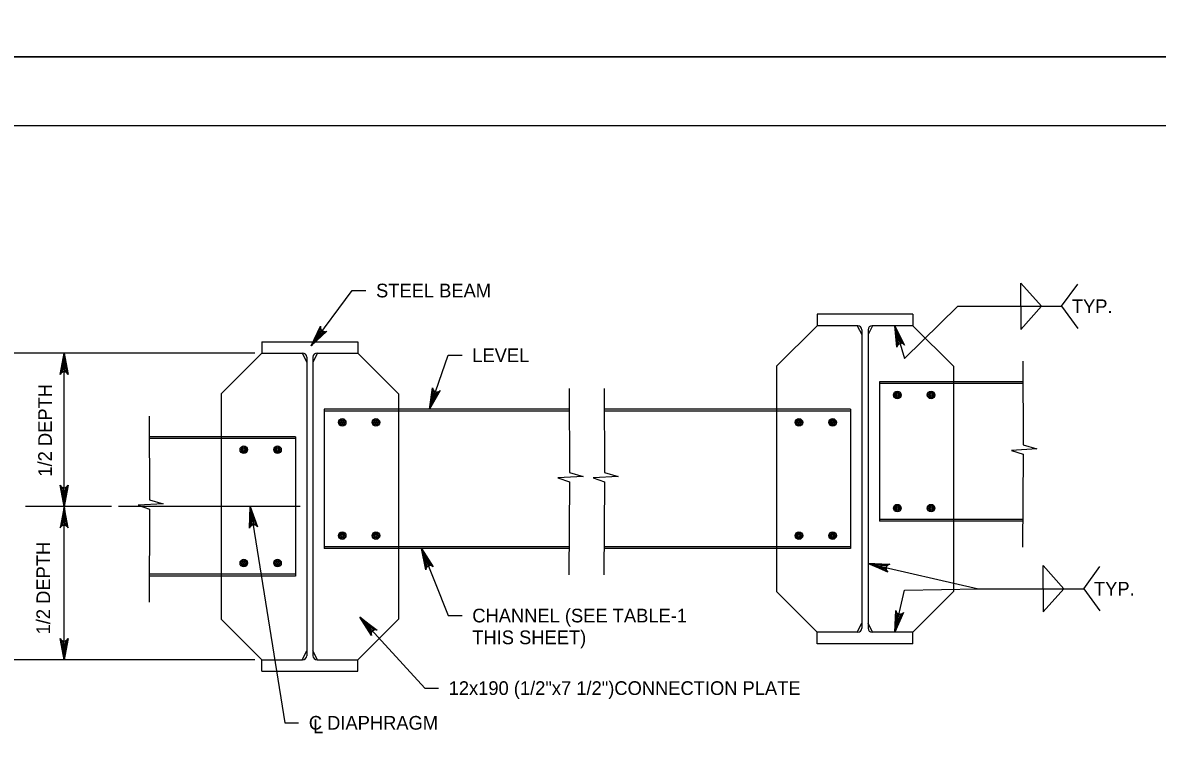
# Model space of a CAD drawing. Extents: x 638175 to 640495, y 294277 to 298435.
# Drawn here: x 639649.2 to 639897.7, y 297690.7 to 297849 of the extents above; entities that cross this region are included whole.
import ezdxf

# ---------------------------------------------------------------- set-up
doc = ezdxf.new("R2010")
doc.units = 0
for name, color, linetype in [('2', 7, 'Continuous'), ('3', 7, 'Continuous'), ('4', 7, 'Continuous'), ('5', 7, 'Continuous'), ('PLT-BNDY', 7, 'Continuous')]:
    doc.layers.add(name, color=color, linetype=linetype)

msp = doc.modelspace()

# ---------------------------------------------------------------- linework, layer by layer
at = {"layer": '2'}
msp.add_line((639316.46, 297826.46), (640102.46, 297826.46), dxfattribs=at)
for points in [[(639658.23, 297776.59), (639659.1, 297771.93), (639658.85, 297772.29), (639658.54, 297772.47), (639658.23, 297772.53), (639657.91, 297772.47), (639657.6, 297772.29), (639657.35, 297771.93), (639658.23, 297776.59), (639657.6, 297772.29), (639657.91, 297772.47), (639658.23, 297776.59), (639658.23, 297772.53), (639658.54, 297772.47), (639658.23, 297776.59), (639658.85, 297772.29)], [(639658.23, 297743.02), (639657.35, 297747.68), (639657.6, 297747.32), (639657.91, 297747.13), (639658.23, 297747.08), (639658.54, 297747.13), (639658.85, 297747.32), (639659.1, 297747.68), (639658.23, 297743.02), (639658.85, 297747.32), (639658.54, 297747.13), (639658.23, 297743.02), (639658.23, 297747.08), (639657.91, 297747.13), (639658.23, 297743.02), (639657.6, 297747.32)], [(639658.23, 297743.02), (639657.35, 297738.36), (639657.6, 297738.71), (639657.91, 297738.9), (639658.23, 297738.95), (639658.54, 297738.9), (639658.85, 297738.71), (639659.1, 297738.36), (639658.23, 297743.02), (639658.85, 297738.71), (639658.54, 297738.9), (639658.23, 297743.02), (639658.23, 297738.95), (639657.91, 297738.9), (639658.23, 297743.02), (639657.6, 297738.71)], [(639658.23, 297709.44), (639657.35, 297714.1), (639657.6, 297713.75), (639657.91, 297713.56), (639658.23, 297713.51), (639658.54, 297713.56), (639658.85, 297713.75), (639659.1, 297714.1), (639658.23, 297709.44), (639658.85, 297713.75), (639658.54, 297713.56), (639658.23, 297709.44), (639658.23, 297713.51), (639657.91, 297713.56), (639658.23, 297709.44), (639657.6, 297713.75)]]:
    msp.add_lwpolyline(points, dxfattribs=at)
at = {"layer": '3'}
for p, q in [((639867.84, 297791.93), (639872.38, 297786.85)), ((639867.84, 297786.85), (639867.84, 297791.93)), ((639876.75, 297786.85), (639880.32, 297791.69)), ((639712.33, 297778.21), (639721.32, 297790.3)), ((639721.32, 297790.3), (639724.32, 297790.3)), ((639842.3, 297775.45), (639854.05, 297786.85)), ((639854.05, 297786.85), (639876.75, 297786.85)), ((639867.84, 297781.76), (639872.38, 297786.85)), ((639867.84, 297786.85), (639867.84, 297781.76)), ((639876.75, 297786.85), (639880.32, 297782.01)), ((639840.22, 297782.6), (639842.3, 297775.45)), ((639700.02, 297776.59), (639634.16, 297776.59)), ((639658.23, 297743.02), (639658.23, 297776.59)), ((639738.25, 297764.29), (639742.4, 297776.14)), ((639742.4, 297776.14), (639745.4, 297776.14)), ((639868.25, 297774.83), (639868.31, 297756.48)), ((639768.85, 297768.82), (639768.91, 297750.46)), ((639776.57, 297768.82), (639776.63, 297750.46)), ((639676.89, 297762.81), (639676.95, 297744.45)), ((639868.31, 297756.48), (639871.31, 297755.6)), ((639871.31, 297755.6), (639865.79, 297755.29)), ((639865.79, 297755.29), (639868.3, 297754.43)), ((639868.3, 297754.43), (639868.18, 297734.08)), ((639771.92, 297749.58), (639766.4, 297749.28)), ((639766.4, 297749.28), (639768.91, 297748.42)), ((639768.91, 297750.46), (639771.92, 297749.58)), ((639779.63, 297749.58), (639774.11, 297749.28)), ((639774.11, 297749.28), (639776.63, 297748.42)), ((639776.63, 297750.46), (639779.63, 297749.58)), ((639768.91, 297748.42), (639768.79, 297728.06)), ((639776.63, 297748.42), (639776.5, 297728.06)), ((639676.95, 297744.45), (639679.96, 297743.57)), ((639668.59, 297743.02), (639649.76, 297743.02)), ((639658.23, 297709.44), (639658.23, 297743.02)), ((639679.96, 297743.57), (639674.44, 297743.26)), ((639674.44, 297743.26), (639676.95, 297742.41)), ((639676.95, 297742.41), (639676.83, 297722.05)), ((639698.98, 297743.02), (639706.59, 297695.63)), ((639736.53, 297733.77), (639742.4, 297719.13)), ((639834.37, 297730.53), (639858.54, 297725)), ((639872.68, 297730.08), (639877.21, 297725)), ((639872.68, 297725), (639872.68, 297730.08)), ((639881.59, 297725), (639885.16, 297729.84)), ((639840.22, 297715.46), (639842.3, 297724.66)), ((639842.3, 297724.66), (639858.54, 297725)), ((639858.54, 297725), (639881.59, 297725)), ((639872.68, 297725), (639872.68, 297719.92)), ((639872.68, 297719.92), (639877.21, 297725)), ((639881.59, 297725), (639885.16, 297720.16)), ((639742.4, 297719.13), (639745.4, 297719.13)), ((639723.05, 297718.78), (639737.22, 297703.23)), ((639700.02, 297709.44), (639634.16, 297709.44)), ((639737.22, 297703.23), (639740.22, 297703.23)), ((639706.59, 297695.63), (639709.59, 297695.63))]:
    msp.add_line(p, q, dxfattribs=at)
for points in [[(639712.33, 297778.21), (639714.41, 297782.47), (639714.39, 297782.04), (639714.53, 297781.7), (639714.75, 297781.47), (639715.03, 297781.33), (639715.4, 297781.29), (639715.81, 297781.43), (639712.33, 297778.21), (639715.4, 297781.29), (639715.03, 297781.33), (639712.33, 297778.21), (639714.75, 297781.47), (639714.53, 297781.7), (639712.33, 297778.21), (639714.39, 297782.04)], [(639840.22, 297782.6), (639842.36, 297778.37), (639842.02, 297778.65), (639841.67, 297778.74), (639841.35, 297778.7), (639841.07, 297778.56), (639840.82, 297778.3), (639840.68, 297777.89), (639840.22, 297782.6), (639840.82, 297778.3), (639841.07, 297778.56), (639840.22, 297782.6), (639841.35, 297778.7), (639841.67, 297778.74), (639840.22, 297782.6), (639842.02, 297778.65)], [(639738.25, 297764.29), (639738.97, 297768.97), (639739.08, 297768.55), (639739.32, 297768.27), (639739.6, 297768.12), (639739.91, 297768.07), (639740.26, 297768.14), (639740.62, 297768.4), (639738.25, 297764.29), (639740.26, 297768.14), (639739.91, 297768.07), (639738.25, 297764.29), (639739.6, 297768.12), (639739.32, 297768.27), (639738.25, 297764.29), (639739.08, 297768.55)], [(639698.98, 297743.02), (639700.58, 297738.55), (639700.28, 297738.87), (639699.94, 297739), (639699.63, 297739.01), (639699.33, 297738.9), (639699.05, 297738.67), (639698.86, 297738.28), (639698.98, 297743.02), (639699.05, 297738.67), (639699.33, 297738.9), (639698.98, 297743.02), (639699.63, 297739.01), (639699.94, 297739), (639698.98, 297743.02), (639700.28, 297738.87)], [(639736.53, 297733.77), (639739.07, 297729.77), (639738.71, 297730.01), (639738.35, 297730.07), (639738.04, 297730), (639737.77, 297729.84), (639737.55, 297729.55), (639737.45, 297729.12), (639736.53, 297733.77), (639737.55, 297729.55), (639737.77, 297729.84), (639736.53, 297733.77), (639738.04, 297730), (639738.35, 297730.07), (639736.53, 297733.77), (639738.71, 297730.01)], [(639834.37, 297730.53), (639839.1, 297730.34), (639838.7, 297730.18), (639838.45, 297729.92), (639838.33, 297729.62), (639838.31, 297729.31), (639838.42, 297728.96), (639838.71, 297728.64), (639834.37, 297730.53), (639838.42, 297728.96), (639838.31, 297729.31), (639834.37, 297730.53), (639838.33, 297729.62), (639838.45, 297729.92), (639834.37, 297730.53), (639838.7, 297730.18)], [(639840.22, 297715.46), (639840.4, 297720.2), (639840.56, 297719.79), (639840.82, 297719.54), (639841.12, 297719.42), (639841.43, 297719.4), (639841.78, 297719.52), (639842.1, 297719.81), (639840.22, 297715.46), (639841.78, 297719.52), (639841.43, 297719.4), (639840.22, 297715.46), (639841.12, 297719.42), (639840.82, 297719.54), (639840.22, 297715.46), (639840.56, 297719.79)], [(639723.05, 297718.78), (639726.83, 297715.92), (639726.4, 297716.02), (639726.05, 297715.95), (639725.78, 297715.78), (639725.59, 297715.53), (639725.48, 297715.18), (639725.54, 297714.75), (639723.05, 297718.78), (639725.48, 297715.18), (639725.59, 297715.53), (639723.05, 297718.78), (639725.78, 297715.78), (639726.05, 297715.95), (639723.05, 297718.78), (639726.4, 297716.02)]]:
    msp.add_lwpolyline(points, dxfattribs=at)
for points in [[(639840.58, 297779.58), (639841.54, 297779.86), (639840.22, 297782.6)], [(639714.52, 297780.32), (639713.72, 297780.92), (639712.33, 297778.21)], [(639657.73, 297773.59), (639658.73, 297773.59), (639658.23, 297776.59)], [(639739.72, 297766.95), (639738.77, 297767.28), (639738.25, 297764.29)], [(639657.73, 297746.02), (639658.73, 297746.02), (639658.23, 297743.02)], [(639657.73, 297740.02), (639658.73, 297740.02), (639658.23, 297743.02)], [(639698.96, 297739.97), (639699.95, 297740.13), (639698.98, 297743.02)], [(639737.18, 297730.8), (639738.11, 297731.18), (639736.52, 297733.77)], [(639837.18, 297729.37), (639837.4, 297730.35), (639834.37, 297730.53)], [(639724.7, 297716.23), (639725.43, 297716.9), (639723.05, 297718.78)], [(639841.37, 297718.27), (639840.4, 297718.5), (639840.22, 297715.46)], [(639657.73, 297712.44), (639658.73, 297712.44), (639658.23, 297709.44)]]:
    msp.add_lwpolyline(points, close=True, dxfattribs=at)
at = {"layer": '4'}
for p, q in [((639844.16, 297785.1), (639823.2, 297785.1)), ((639823.2, 297782.6), (639814.29, 297773.7)), ((639832.1, 297782.6), (639823.2, 297782.6)), ((639832, 297782.6), (639832.99, 297780.64)), ((639832.99, 297781.71), (639832.99, 297716.35)), ((639835.35, 297782.6), (639834.37, 297780.64)), ((639834.37, 297781.71), (639834.37, 297716.35)), ((639844.16, 297782.6), (639835.26, 297782.6)), ((639844.16, 297782.6), (639853.07, 297773.7)), ((639701.58, 297779.09), (639722.55, 297779.09)), ((639701.58, 297776.59), (639692.67, 297767.68)), ((639701.58, 297776.59), (639710.49, 297776.59)), ((639710.39, 297776.59), (639711.38, 297774.62)), ((639713.74, 297776.59), (639712.75, 297774.62)), ((639713.64, 297776.59), (639722.55, 297776.59)), ((639722.55, 297776.59), (639731.46, 297767.68)), ((639711.38, 297775.7), (639711.38, 297710.33)), ((639712.75, 297775.7), (639712.75, 297710.33)), ((639814.29, 297773.7), (639814.29, 297764.29)), ((639853.07, 297773.7), (639853.07, 297770.3)), ((639836.83, 297770.3), (639836.83, 297739.79)), ((639853.07, 297770.3), (639853.07, 297739.79)), ((639692.67, 297767.68), (639692.67, 297758.27)), ((639731.46, 297767.68), (639731.46, 297764.29)), ((639715.21, 297764.29), (639715.21, 297733.77)), ((639731.46, 297764.29), (639731.46, 297733.77)), ((639814.29, 297764.29), (639814.29, 297733.77)), ((639830.53, 297764.29), (639830.53, 297733.77)), ((639692.67, 297758.27), (639692.67, 297727.76)), ((639708.92, 297758.27), (639708.92, 297727.76)), ((639853.07, 297739.79), (639853.07, 297724.37)), ((639731.46, 297733.77), (639731.46, 297718.35)), ((639814.29, 297733.77), (639814.29, 297724.37)), ((639692.67, 297727.76), (639692.67, 297718.35)), ((639814.29, 297724.37), (639823.2, 297715.46)), ((639844.16, 297715.46), (639853.07, 297724.37)), ((639692.67, 297718.35), (639701.58, 297709.44)), ((639722.55, 297709.44), (639731.46, 297718.35)), ((639832, 297715.46), (639832.99, 297717.43)), ((639835.35, 297715.46), (639834.37, 297717.43)), ((639832.1, 297715.46), (639823.2, 297715.46)), ((639844.16, 297715.46), (639835.26, 297715.46)), ((639844.16, 297712.96), (639823.2, 297712.96)), ((639701.58, 297709.44), (639710.49, 297709.44)), ((639710.39, 297709.44), (639711.38, 297711.41)), ((639713.74, 297709.44), (639712.75, 297711.41)), ((639713.64, 297709.44), (639722.55, 297709.44)), ((639701.58, 297706.94), (639722.55, 297706.94))]:
    msp.add_line(p, q, dxfattribs=at)
for centre, radius in [((639840.76, 297767.45), 0.833), ((639840.76, 297767.45), 0.625), ((639840.76, 297767.45), 0.417), ((639840.76, 297767.45), 0.208), ((639848.15, 297767.45), 0.833), ((639848.15, 297767.45), 0.625), ((639848.15, 297767.45), 0.417), ((639848.15, 297767.45), 0.208), ((639719.15, 297761.43), 0.833), ((639719.15, 297761.43), 0.625), ((639719.15, 297761.43), 0.417), ((639719.15, 297761.43), 0.208), ((639726.53, 297761.43), 0.833), ((639726.53, 297761.43), 0.625), ((639726.53, 297761.43), 0.417), ((639726.53, 297761.43), 0.208), ((639819.21, 297761.43), 0.833), ((639819.21, 297761.43), 0.625), ((639819.21, 297761.43), 0.417), ((639819.21, 297761.43), 0.208), ((639826.59, 297761.43), 0.833), ((639826.59, 297761.43), 0.625), ((639826.59, 297761.43), 0.417), ((639826.59, 297761.43), 0.208), ((639697.6, 297755.42), 0.833), ((639697.6, 297755.42), 0.625), ((639697.6, 297755.42), 0.417), ((639697.6, 297755.42), 0.208), ((639704.98, 297755.42), 0.833), ((639704.98, 297755.42), 0.625), ((639704.98, 297755.42), 0.417), ((639704.98, 297755.42), 0.208), ((639840.76, 297742.64), 0.833), ((639840.76, 297742.64), 0.625), ((639840.76, 297742.64), 0.417), ((639840.76, 297742.64), 0.208), ((639848.15, 297742.64), 0.833), ((639848.15, 297742.64), 0.625), ((639848.15, 297742.64), 0.417), ((639848.15, 297742.64), 0.208), ((639719.15, 297736.63), 0.833), ((639719.15, 297736.63), 0.625), ((639719.15, 297736.63), 0.417), ((639719.15, 297736.63), 0.208), ((639726.53, 297736.63), 0.833), ((639726.53, 297736.63), 0.625), ((639726.53, 297736.63), 0.417), ((639726.53, 297736.63), 0.208), ((639819.21, 297736.63), 0.833), ((639819.21, 297736.63), 0.625), ((639819.21, 297736.63), 0.417), ((639819.21, 297736.63), 0.208), ((639826.59, 297736.63), 0.833), ((639826.59, 297736.63), 0.625), ((639826.59, 297736.63), 0.417), ((639826.59, 297736.63), 0.208), ((639697.6, 297730.62), 0.833), ((639697.6, 297730.62), 0.625), ((639697.6, 297730.62), 0.417), ((639697.6, 297730.62), 0.208), ((639704.98, 297730.62), 0.833), ((639704.98, 297730.62), 0.625), ((639704.98, 297730.62), 0.417), ((639704.98, 297730.62), 0.208)]:
    msp.add_circle(centre, radius, dxfattribs=at)
for centre, start, end in [((639832.1, 297781.71), 0, 90), ((639835.25, 297781.71), 90, 180), ((639710.49, 297775.7), 0, 90), ((639713.64, 297775.7), 90, 180), ((639832.1, 297716.35), 270, 0), ((639835.25, 297716.35), 180, 270), ((639710.49, 297710.33), 270, 0), ((639713.64, 297710.33), 180, 270)]:
    msp.add_arc(centre, 0.889, start, end, dxfattribs=at)
at = {"layer": '5'}
for p, q in [((639823.2, 297785.1), (639823.2, 297782.6)), ((639844.16, 297785.1), (639844.16, 297782.6)), ((639701.58, 297779.09), (639701.58, 297776.59)), ((639722.55, 297779.09), (639722.55, 297776.59)), ((639868.26, 297770.3), (639836.83, 297770.3)), ((639868.26, 297769.91), (639836.83, 297769.91)), ((639768.87, 297764.29), (639715.21, 297764.29)), ((639768.87, 297763.89), (639715.21, 297763.89)), ((639830.53, 297764.29), (639776.58, 297764.29)), ((639830.53, 297763.89), (639776.58, 297763.89)), ((639708.92, 297758.27), (639676.9, 297758.27)), ((639708.92, 297757.88), (639676.91, 297757.88)), ((639709.95, 297743.02), (639670.16, 297743.02)), ((639868.22, 297740.18), (639836.83, 297740.18)), ((639868.22, 297739.79), (639836.83, 297739.79)), ((639768.83, 297734.17), (639715.21, 297734.17)), ((639830.53, 297734.17), (639776.54, 297734.17)), ((639768.82, 297733.77), (639715.21, 297733.77)), ((639830.53, 297733.77), (639776.54, 297733.77)), ((639708.92, 297728.15), (639676.86, 297728.15)), ((639708.92, 297727.76), (639676.86, 297727.76)), ((639823.2, 297712.96), (639823.2, 297715.46)), ((639844.16, 297712.96), (639844.16, 297715.46)), ((639701.58, 297706.94), (639701.58, 297709.44)), ((639722.55, 297706.94), (639722.55, 297709.44))]:
    msp.add_line(p, q, dxfattribs=at)
at = {"layer": 'PLT-BNDY'}
for points in [[(639276.46, 298435.46), (640117.46, 298435.46), (640117.46, 297841.46), (639276.46, 297841.46)], [(639276.46, 297841.46), (640117.46, 297841.46), (640117.46, 297247.46), (639276.46, 297247.46)]]:
    msp.add_lwpolyline(points, close=True, dxfattribs=at)

# ---------------------------------------------------------------- texts
at = {"layer": '3'}
for s, p in [('STEEL BEAM', (639726.57, 297788.8)), ('TYP.', (639879, 297785.35)), ('LEVEL', (639747.65, 297774.64)), ('TYP.', (639883.84, 297723.5)), ('CHANNEL (SEE TABLE-1', (639747.65, 297717.62)), ('THIS SHEET)', (639747.65, 297712.85)), ('12x190 (1/2"x7 1/2")CONNECTION PLATE', (639742.47, 297701.73)), ('C DIAPHRAGM', (639711.84, 297694.13)), ('L', (639712.78, 297693.36))]:
    msp.add_text(s, height=3, dxfattribs=at).set_placement(p)
for p in [(639655.56, 297749.54), (639655.17, 297714.99)]:
    msp.add_text('1/2 DEPTH', height=3, rotation=90, dxfattribs=at).set_placement(p)

doc.saveas('drawing.dxf')
